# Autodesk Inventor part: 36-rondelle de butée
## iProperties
Created: 2011-02
Part Number: 36-rondelle de butée
Document SubType Name: Modeling
Designer: eric
Density: 1 g/cm^3
Author: eric
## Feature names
1. Base1
